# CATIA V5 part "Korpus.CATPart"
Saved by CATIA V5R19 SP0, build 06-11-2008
Part number: Korpus
Bounding box of the stored display mesh (mm): x -44.334 to 1985.666, y -2189.086 to 50.914, z 0 to 2150
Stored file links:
  E:\Podręcznik\catia\Machine\Korpus.CATPart
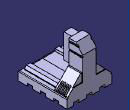
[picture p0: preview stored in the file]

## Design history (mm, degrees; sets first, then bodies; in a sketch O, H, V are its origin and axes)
Body1 (main body)
  Sketch1 on xy-plane, origin (0, 0, 0), H (1, 0, 0), V (0, 1, 0)
    line L1 (-44.3342, 50.9137) -> (1985.6658, 50.9137)
    line L2 (1985.6658, 50.9137) -> (1985.6658, -2189.0863)
    line L3 (1985.6658, -2189.0863) -> (-44.3342, -2189.0863)
    line L4 (-44.3342, -2189.0863) -> (-44.3342, 50.9137)
    length L1 = 2030
    length L4 = 2240
    horizontal: L1 H, L3 H
    vertical: L2 V, L4 V
  Pad1: profile Sketch1, direction (0, 0, 1), length 400
  Sketch2 on end face of Pad1, origin (0, 0, 400), H (1, 0, 0), V (0, 1, 0)
    line L1 (655.6658, 50.9137) -> (1285.6658, 50.9137)
    line L2 (1285.6658, 50.9137) -> (1285.6658, -579.0863)
    line L3 (1285.6658, -579.0863) -> (655.6658, -579.0863)
    line L4 (655.6658, -579.0863) -> (655.6658, 50.9137)
    reference projected line E1 (3175.6658, 50.9137) -> (-44.3342, 50.9137) from edge [face of Pad1 from Sketch1.L1 | end face of Pad1]
    reference projected line E2 (1985.6658, -2189.0863) -> (1985.6658, 50.9137) from edge [face of Pad1 from Sketch1.L2 | end face of Pad1]
    length L2 = 630
    length L1 = 630
    distance L2 E2 = 700
    horizontal: L1 H, L3 H
    vertical: L2 V, L4 V
    coincidence: L1 E1
  Pad2: profile Sketch2, direction (0, 0, 1), length 1750
  Sketch3 on face of Pad2, origin (0, 50.9137, 0), H (-1, 0, 0), V (0, 0, 1)
    line L1 (-1285.6658, 395.2078) -> (-1285.6658, 1085.2078)
    line L2 (-1285.6658, 395.2078) -> (-1955.6658, 395.2078)
    line L3 (-1285.6658, 1085.2078) -> (-1345.9583, 1085.2078)
    line L4 (-1955.6658, 395.2078) -> (-1955.6658, 459.4068)
    line L5 (-1955.6658, 459.4068) -> (-1345.9583, 1085.2078)
    line L6 (-655.6658, 395.2078) -> (-655.6658, 1085.2078)
    line L7 (-655.6658, 395.2078) -> (14.3342, 395.2078)
    line L8 (-655.6658, 1085.2078) -> (-595.3734, 1085.2078)
    line L9 (14.3342, 395.2078) -> (14.3342, 459.4068)
    line L10 (14.3342, 459.4068) -> (-595.3734, 1085.2078)
    length L1 = 690
    length L2 = 670
    vertical: L1 V, L4 V
    coincidence: L1, L2, L1, L6
    horizontal: L2 H, L3 H
  Pad3: profile Sketch3, direction (0, -1, 0), length 600
  Sketch4 on face of Pad3, origin (0, 50.9137, 0), H (-1, 0, 0), V (0, 0, 1)
    line L1 (-1285.6658, 700) -> (-1285.6658, 1390)
    line L2 (-1285.6658, 700) -> (-1955.6658, 700)
    line L3 (-1285.6658, 1390) -> (-1345.9583, 1390)
    line L4 (-1955.6658, 700) -> (-1955.6658, 764.199)
    line L5 (-655.6658, 700) -> (-655.6658, 1390)
    line L6 (-1955.6658, 764.199) -> (-1345.9583, 1390)
    line L7 (-655.6658, 700) -> (14.3342, 700)
    line L8 (-655.6658, 1390) -> (-595.3734, 1390)
    line L9 (14.3342, 700) -> (14.3342, 764.199)
    line L10 (14.3342, 764.199) -> (-595.3734, 1390)
    length L1 = 690
    horizontal: L3 H
    vertical: L4 V
  Pocket1: profile Sketch4, direction (0, -1, 0), length 30
  Sketch5 on face of Pad3 from Sketch3.L3, origin (0, 0, 1085.2078), H (1, 0, 0), V (0, 1, 0)
    construction line L1 (1993.939, -84.0863) -> (1732.2759, -84.0863)
    line L2 (1993.939, -124.0863) -> (1732.2759, -124.0863)
    line L3 (1732.2759, -44.0863) -> (1993.939, -44.0863)
    arc A1 centre (1732.2759, -84.0863) radius 40 from (1732.2759, -124.0863) to (1732.2759, -44.0863) cw
    arc A2 centre (1993.939, -84.0863) radius 40 from (1993.939, -44.0863) to (1993.939, -124.0863) cw
    point P3 (1993.939, -124.0863)
    point P4 (1732.2759, -124.0863)
    point P5 (1732.2759, -44.0863)
    point P6 (1993.939, -44.0863)
    construction line L4 (1993.939, -204.0863) -> (1732.2759, -204.0863)
    point P9 (1993.939, -244.0863)
    point P10 (1732.2759, -244.0863)
    point P11 (1732.2759, -164.0863)
    point P12 (1993.939, -164.0863)
    line L5 (1993.939, -244.0863) -> (1732.2759, -244.0863)
    line L6 (1732.2759, -164.0863) -> (1993.939, -164.0863)
    arc A3 centre (1732.2759, -204.0863) radius 40 from (1732.2759, -244.0863) to (1732.2759, -164.0863) cw
    arc A4 centre (1993.939, -204.0863) radius 40 from (1993.939, -164.0863) to (1993.939, -244.0863) cw
    construction line L7 (1993.939, -324.0863) -> (1732.2759, -324.0863)
    point P15 (1993.939, -364.0863)
    point P16 (1732.2759, -364.0863)
    point P17 (1732.2759, -284.0863)
    point P18 (1993.939, -284.0863)
    line L8 (1993.939, -364.0863) -> (1732.2759, -364.0863)
    line L9 (1732.2759, -284.0863) -> (1993.939, -284.0863)
    arc A5 centre (1732.2759, -324.0863) radius 40 from (1732.2759, -364.0863) to (1732.2759, -284.0863) cw
    arc A6 centre (1993.939, -324.0863) radius 40 from (1993.939, -284.0863) to (1993.939, -364.0863) cw
    construction line L10 (1993.939, -444.0863) -> (1732.2759, -444.0863)
    point P21 (1993.939, -484.0863)
    point P22 (1732.2759, -484.0863)
    point P23 (1732.2759, -404.0863)
    point P24 (1993.939, -404.0863)
    line L11 (1993.939, -484.0863) -> (1732.2759, -484.0863)
    line L12 (1732.2759, -404.0863) -> (1993.939, -404.0863)
    arc A7 centre (1732.2759, -444.0863) radius 40 from (1732.2759, -484.0863) to (1732.2759, -404.0863) cw
    arc A8 centre (1993.939, -444.0863) radius 40 from (1993.939, -404.0863) to (1993.939, -484.0863) cw
    reference projected line E1 (1985.6658, 50.9137) -> (-44.3342, 50.9137) from edge [face of Pad3 | face of Pocket1]
    axis line L13 (970.6658, -359.4282) -> (970.6658, -674.4282)
    reference projected line E2 (1285.6658, -579.0863) -> (1285.6658, 50.9137) from edge [face of Pocket1 | end face of Pad2]
    construction line L14 (-52.6073, -84.0863) -> (209.0558, -84.0863)
    point P29 (-52.6073, -124.0863)
    point P30 (209.0558, -124.0863)
    point P31 (209.0558, -44.0863)
    point P32 (-52.6073, -44.0863)
    construction line L15 (-52.6073, -204.0863) -> (209.0558, -204.0863)
    point P35 (-52.6073, -244.0863)
    point P36 (209.0558, -244.0863)
    point P37 (209.0558, -164.0863)
    point P38 (-52.6073, -164.0863)
    construction line L16 (-52.6073, -324.0863) -> (209.0558, -324.0863)
    point P41 (-52.6073, -364.0863)
    point P42 (209.0558, -364.0863)
    point P43 (209.0558, -284.0863)
    point P44 (-52.6073, -284.0863)
    construction line L17 (-52.6073, -444.0863) -> (209.0558, -444.0863)
    point P47 (-52.6073, -484.0863)
    point P48 (209.0558, -484.0863)
    point P49 (209.0558, -404.0863)
    point P50 (-52.6073, -404.0863)
    line L18 (-52.6073, -124.0863) -> (209.0558, -124.0863)
    line L19 (209.0558, -44.0863) -> (-52.6073, -44.0863)
    arc A9 centre (209.0558, -84.0863) radius 40 from (209.0558, -124.0863) to (209.0558, -44.0863) ccw
    arc A10 centre (-52.6073, -84.0863) radius 40 from (-52.6073, -44.0863) to (-52.6073, -124.0863) ccw
    line L20 (-52.6073, -244.0863) -> (209.0558, -244.0863)
    line L21 (209.0558, -164.0863) -> (-52.6073, -164.0863)
    arc A11 centre (209.0558, -204.0863) radius 40 from (209.0558, -244.0863) to (209.0558, -164.0863) ccw
    arc A12 centre (-52.6073, -204.0863) radius 40 from (-52.6073, -164.0863) to (-52.6073, -244.0863) ccw
    line L22 (-52.6073, -364.0863) -> (209.0558, -364.0863)
    line L23 (209.0558, -284.0863) -> (-52.6073, -284.0863)
    arc A13 centre (209.0558, -324.0863) radius 40 from (209.0558, -364.0863) to (209.0558, -284.0863) ccw
    arc A14 centre (-52.6073, -324.0863) radius 40 from (-52.6073, -284.0863) to (-52.6073, -364.0863) ccw
    line L24 (-52.6073, -484.0863) -> (209.0558, -484.0863)
    line L25 (209.0558, -404.0863) -> (-52.6073, -404.0863)
    arc A15 centre (209.0558, -444.0863) radius 40 from (209.0558, -484.0863) to (209.0558, -404.0863) ccw
    arc A16 centre (-52.6073, -444.0863) radius 40 from (-52.6073, -404.0863) to (-52.6073, -484.0863) ccw
    distance L3 L2 = 80
    distance L2 L6 = 40
    distance L9 L5 = 40
    distance L8 L12 = 40
    distance L3 E1 = 95
    distance L13 E2 = 315
    horizontal: L1 H
    tangency: A1 L2, A2 L2, A1 L3, A2 L3
    parallelism: L1 L2
    vertical: L13 V
    symmetry: L1 L14 L13, P3 P29 L13, P4 P30 L13, P5 P31 L13, P6 P32 L13, L4 L15 L13, P9 P35 L13, P10 P36 L13, P11 P37 L13, P12 P38 L13, L7 L16 L13, P15 P41 L13, P16 P42 L13, P17 P43 L13, P18 P44 L13, L10 L17 L13, P21 P47 L13, P22 P48 L13, P23 P49 L13, P24 P50 L13, L2 L18 L13, L3 L19 L13, A1 A9 L13, A2 A10 L13, L5 L20 L13, L6 L21 L13, A3 A11 L13, A4 A12 L13, L8 L22 L13, L9 L23 L13, A5 A13 L13, A6 A14 L13, L11 L24 L13, L12 L25 L13, A7 A15 L13, A8 A16 L13
  Pocket2: profile Sketch5, direction (0, 0, -1), length 650
  Plane1: type Offset, Offset 100, RefPlane face of Pad1 from Sketch1.L3
  Sketch6 on Plane1, origin (0, -2089.0863, 0), H (-1, 0, 0), V (0, 0, 1)
    axis line L1 (-970.6658, 2489.1741) -> (-970.6658, 494.8887)
    line L2 (-970.6658, 391.1226) -> (-1798.9652, 391.1226)
    line L3 (-1798.9652, 391.1226) -> (-1798.9652, 431.1283)
    line L4 (-1798.9652, 431.1283) -> (-1715.0778, 541.8107)
    line L5 (-1715.0778, 541.8107) -> (-1532.6558, 541.8107)
    line L6 (-1532.6558, 541.8107) -> (-1532.6558, 431.1283)
    line L7 (-1532.6558, 431.1283) -> (-970.6658, 431.1283)
    line L8 (-970.6658, 391.1226) -> (-142.3665, 391.1226)
    line L9 (-142.3665, 391.1226) -> (-142.3665, 431.1283)
    line L10 (-142.3665, 431.1283) -> (-226.2539, 541.8107)
    line L11 (-226.2539, 541.8107) -> (-408.6759, 541.8107)
    line L12 (-408.6759, 541.8107) -> (-408.6759, 431.1283)
    line L13 (-408.6759, 431.1283) -> (-970.6658, 431.1283)
  Pad4: profile Sketch6, direction (0, 1, 0), length 1550
  Sketch7 on face of Pad2 from Sketch2.L3, origin (0, -579.0863, 0), H (1, 0, 0), V (0, 0, 1)
    line L1 (765.6658, 2111.5234) -> (1115.6658, 2111.5234)
    line L2 (1115.6658, 2111.5234) -> (1115.6658, 1000)
    line L3 (1115.6658, 1000) -> (765.6658, 1000)
    line L4 (765.6658, 1000) -> (765.6658, 2111.5234)
    reference projected line E1 (-44.3342, 0) -> (1985.6658, 0) from edge [start face of Pad1 | face of Pad1 from Sketch1.L3]
    reference projected line E2 (1285.6658, 700) -> (1285.6658, 2450) from edge [face of Pocket1 | face of Pad2 from Sketch2.L3]
    distance L3 E1 = 1000
    length L1 = 350
    distance L2 E2 = 170
    horizontal: L1 H
    vertical: L2 V, L4 V
  Sketch8 on face of Pad1 from Sketch1.L3, origin (0, -2189.0863, 0), H (1, 0, 0), V (0, 0, 1)
    line L1 (860.4044, 120) -> (1110.6658, 120)
    line L2 (1110.6658, 120) -> (1110.6658, 0)
    line L3 (1110.6658, 0) -> (860.4044, 0)
    line L4 (860.4044, 0) -> (860.4044, 120)
    line L5 (1460.6658, 120) -> (1705.58, 120)
    line L6 (1705.58, 120) -> (1705.58, 0)
    line L7 (1705.58, 0) -> (1460.6658, 0)
    line L8 (1460.6658, 0) -> (1460.6658, 120)
    line L9 (265.4902, 120) -> (510.4044, 120)
    line L10 (510.4044, 120) -> (510.4044, 0)
    line L11 (510.4044, 0) -> (265.4902, 0)
    line L12 (265.4902, 0) -> (265.4902, 120)
    length L2 = 120
    distance L2 = 875
    distance L8 L2 = 350
    distance L4 L10 = 350
    horizontal: L1 H, L3 H
    vertical: L2 V, L4 V
    coincidence: L3
  Pocket3: profile Sketch8, direction (0, 1, 0), through (limit type 3)
  Sketch9 on face of Pad1 from Sketch1.L2, origin (1985.6658, 0, 0), H (0, 1, 0), V (0, 0, 1)
    construction line L1 through (-2047.4688, -0.6211) direction (1, 0)
    line L2 (-1187.0644, 119.3789) -> (-936.803, 119.3789)
    line L3 (-936.803, -0.6211) -> (-1187.0644, -0.6211)
    construction line L4 through (-2046.9228, 4.5888) direction (0, 1)
    line L5 (-936.803, 119.3789) -> (-936.803, -0.6211)
    line L6 (-1187.0644, -0.6211) -> (-1187.0644, 119.3789)
    line L7 (-586.803, -0.6211) -> (-586.803, 119.3789)
    line L8 (-1537.0644, 119.3789) -> (-1537.0644, -0.6211)
    point P1 (-2047.4688, -0.6211)
    line L9 (-586.803, 119.3789) -> (-341.8888, 119.3789)
    line L10 (-341.8888, 119.3789) -> (-341.8888, -0.6211)
    line L11 (-341.8888, -0.6211) -> (-586.803, -0.6211)
    line L12 (-1781.9786, 119.3789) -> (-1537.0644, 119.3789)
    line L13 (-1537.0644, -0.6211) -> (-1781.9786, -0.6211)
    line L14 (-1781.9786, -0.6211) -> (-1781.9786, 119.3789)
    length L5 = 120
    distance L7 L5 = 350
    distance L6 L8 = 350
    horizontal: L2 L1, L3 L1
    vertical: L5 L4, L6 L4
  Pocket4: profile Sketch9, direction (-1, 0, 0), through (limit type 3)
  Sketch10 on face of Pocket1, origin (1285.6658, 0, 0), H (0, 1, 0), V (0, 0, 1)
    line L1 (-437.1161, 2385.626) -> (135.2679, 1667.6128)
    line L2 (135.2679, 1667.6128) -> (401.5818, 2232.0996)
    line L3 (401.5818, 2232.0996) -> (-437.1161, 2385.626)
  Pocket5: profile Sketch10, direction (-1, 0, 0), through (limit type 3)
  Sketch11 on face of Pocket1, origin (1285.6658, 0, 0), H (0, 1, 0), V (0, 0, 1)
    line L1 (-613.3402, 2058.633) -> (105.3302, 2058.633)
    line L2 (105.3302, 2058.633) -> (105.3302, 1990.1354)
    line L3 (105.3302, 1990.1354) -> (-613.3402, 1990.1354)
    line L4 (-613.3402, 1990.1354) -> (-613.3402, 2058.633)
    line L5 (-629.0239, 1730.3371) -> (89.6465, 1730.3371)
    line L6 (89.6465, 1730.3371) -> (89.6465, 1661.8395)
    line L7 (89.6465, 1661.8395) -> (-629.0239, 1661.8395)
    line L8 (-629.0239, 1661.8395) -> (-629.0239, 1730.3371)
    horizontal: L1 H, L3 H
    vertical: L2 V, L4 V
  Pocket6: profile Sketch11, direction (-1, 0, 0), length 30
  Sketch12 on face of Pocket1, origin (655.6658, 0, 0), H (0, -1, 0), V (0, 0, 1)
    line L1 (-69.5211, 2058.633) -> (649.1493, 2058.633)
    line L2 (649.1493, 1990.1354) -> (-69.5211, 1990.1354)
    line L3 (649.1493, 2058.633) -> (649.1493, 1990.1354)
    line L4 (-69.5211, 1990.1354) -> (-69.5211, 2058.633)
    line L5 (-85.2048, 1730.3371) -> (633.4656, 1730.3371)
    line L6 (633.4656, 1730.3371) -> (633.4656, 1661.8395)
    line L7 (633.4656, 1661.8395) -> (-85.2048, 1661.8395)
    line L8 (-85.2048, 1661.8395) -> (-85.2048, 1730.3371)
    horizontal: L1 H, L2 H
    vertical: L3 V, L4 V
  Pocket7: profile Sketch12, direction (1, 0, 0), length 30
  Fillet1: radius 30, on edge [face of Pad1 from Sketch1.L2 | face of Pocket1]; edge [face of Pad1 from Sketch1.L3 | face of Pocket1]; edge [face of Pad1 from Sketch1.L4 | face of Pocket1]
  Pad5: profile Sketch7, direction (0, -1, 0), length 400
  Plane2: type Offset, Offset 100, RefPlane face of Pad1 from Sketch1.L3
  Sketch13 on face of Pad2 from Sketch2.L3, origin (0, -579.0863, 1279.0863), H (1, 0, 0), V (0, 0, 1)
    line L1 (655.6658, -879.0863) -> (1285.6658, -879.0863)
    line L2 (1285.6658, -879.0863) -> (1285.6658, -1509.0863)
    line L3 (1285.6658, -1509.0863) -> (655.6658, -1509.0863)
    line L4 (655.6658, -1509.0863) -> (655.6658, -879.0863)
    reference projected line E1 (1985.6658, -879.0863) -> (-44.3342, -879.0863) from edge [face of Pad1 from Sketch1.L1 | end face of Pad1]
    reference projected point E2 (1985.6658, -879.0863) from edge [face of Pad1 from Sketch1.L2 | end face of Pad1]
    length L2 = 630
    length L1 = 630
    distance L2 E2 = 700
    horizontal: L1 H, L3 H
    vertical: L2 V, L4 V
    coincidence: L1 E1
  Pad6: profile Sketch13, direction (0, -1, 0), length 1750
Current feature: Pad5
